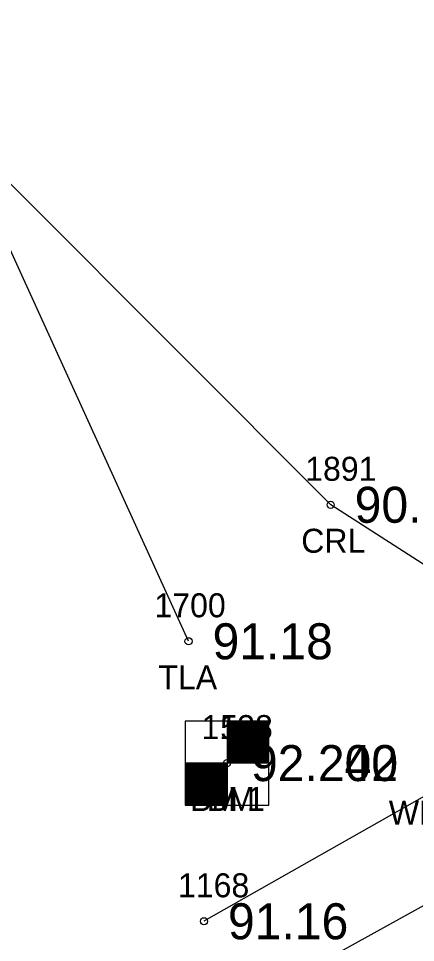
# Model space of a CAD drawing. Extents: x 2529517 to 2532038, y 935000 to 936944.
# Drawn here: x 2531058.87 to 2531075.43, y 935944.18 to 935982.7 of the extents above; entities that cross this region are included whole.
import ezdxf

# ---------------------------------------------------------------- set-up
doc = ezdxf.new("R2010")
doc.units = 0
for name, color, linetype in [('RD_EX_H2O', 7, 'Continuous'), ('RD_EX_H2O_txCode', 7, 'Continuous'), ('RD_EX_Road', 7, 'Continuous'), ('RD_EX_TX_H2O_ELEV', 7, 'Continuous'), ('RD_EX_TX_UT_ELEV', 7, 'Continuous'), ('RD_EX_TX_VEG_ELEV', 7, 'Continuous'), ('RD_EX_UT', 7, 'Continuous'), ('RD_EX_UT_txCode', 7, 'Continuous'), ('RD_EX_VEG', 7, 'Continuous'), ('RD_EX_VEG_txCode', 7, 'Continuous'), ('RD_HC_Survey', 7, 'Continuous'), ('RD_HC_Survey_ELEV', 7, 'Continuous'), ('RD_HC_Survey_txCode', 7, 'Continuous'), ('RD_SMD_Locator', 7, 'Continuous')]:
    doc.layers.add(name, color=color, linetype=linetype)

msp = doc.modelspace()

# ---------------------------------------------------------------- linework, layer by layer
at = {"layer": 'RD_EX_H2O'}
msp.add_lwpolyline([(2531078.875, 935952.281), (2531078.875, 935952.281), (2531082.899, 935955.367), (2531071.893, 935962.427), (2531052.521, 935981.817), (2531042.661, 936018.537), (2531050.401, 936038.586), (2531079.351, 936050.478), (2531076.459, 936052.289), (2531062.769, 936059.407), (2531060.273, 936060.115), (2531061.981, 936077.759), (2531053.988, 936081.477), (2531023.23, 936060.573), (2531009.04, 936063.638), (2530981.915, 936072.848), (2530952.276, 936069.689), (2530922.526, 936086.42), (2530896.36, 936118.007), (2530886.535, 936120.086), (2530870.436, 936126.503), (2530844.881, 936119.109), (2530827.398, 936131.929), (2530794.882, 936161.74)], dxfattribs=at)
at = {"layer": 'RD_EX_Road'}
msp.add_lwpolyline([(2530213.129, 935600.159), (2530313.796, 935600.808), (2530414.146, 935601.135), (2530426.724, 935601.431), (2530429.462, 935603.551), (2530467.667, 935608.622), (2530486.463, 935612.382), (2530518.022, 935622.553), (2530522.163, 935623.679), (2530567.909, 935646.012), (2530609.299, 935670.154), (2530695.461, 935720.024), (2530775.853, 935769.269), (2530868.285, 935824.026), (2530924.837, 935856.951), (2530956.207, 935875.821), (2531040.717, 935926.378), (2531079.452, 935947.762)], dxfattribs=at)
at = {"layer": 'RD_EX_UT'}
msp.add_line((2531077.223, 935951.092), (2531066.609, 935945.067), dxfattribs=at)
at = {"layer": 'RD_EX_VEG'}
msp.add_lwpolyline([(2531065.966, 935956.737), (2531029.723, 936036.27), (2530913.111, 935955.889), (2530857.851, 935929.004), (2530845.595, 935970.773)], dxfattribs=at)
at = {"layer": 'RD_HC_Survey'}
for p, q in [((2531067.569, 935953.41), (2531067.569, 935949.91)), ((2531067.569, 935953.41), (2531067.569, 935949.91)), ((2531067.586, 935953.41), (2531067.586, 935951.66)), ((2531067.586, 935953.41), (2531067.586, 935951.66)), ((2531067.611, 935953.41), (2531067.611, 935951.66)), ((2531067.611, 935953.41), (2531067.611, 935951.66)), ((2531067.636, 935953.41), (2531067.636, 935951.66)), ((2531067.636, 935953.41), (2531067.636, 935951.66)), ((2531067.661, 935953.41), (2531067.661, 935951.66)), ((2531067.661, 935953.41), (2531067.661, 935951.66)), ((2531067.685, 935953.41), (2531067.685, 935951.66)), ((2531067.685, 935953.41), (2531067.685, 935951.66)), ((2531067.71, 935953.41), (2531067.71, 935951.66)), ((2531067.71, 935953.41), (2531067.71, 935951.66)), ((2531067.735, 935953.41), (2531067.735, 935951.66)), ((2531067.735, 935953.41), (2531067.735, 935951.66)), ((2531067.76, 935953.41), (2531067.76, 935951.66)), ((2531067.76, 935953.41), (2531067.76, 935951.66)), ((2531067.784, 935953.41), (2531067.784, 935951.66)), ((2531067.784, 935953.41), (2531067.784, 935951.66)), ((2531067.809, 935953.41), (2531067.809, 935951.66)), ((2531067.809, 935953.41), (2531067.809, 935951.66)), ((2531067.834, 935953.41), (2531067.834, 935951.66)), ((2531067.834, 935953.41), (2531067.834, 935951.66)), ((2531067.859, 935953.41), (2531067.859, 935951.66)), ((2531067.859, 935953.41), (2531067.859, 935951.66)), ((2531067.883, 935953.41), (2531067.883, 935951.66)), ((2531067.883, 935953.41), (2531067.883, 935951.66)), ((2531067.908, 935953.41), (2531067.908, 935951.66)), ((2531067.908, 935953.41), (2531067.908, 935951.66)), ((2531067.933, 935953.41), (2531067.933, 935951.66)), ((2531067.933, 935953.41), (2531067.933, 935951.66)), ((2531067.958, 935953.41), (2531067.958, 935951.66)), ((2531067.958, 935953.41), (2531067.958, 935951.66)), ((2531067.982, 935953.41), (2531067.982, 935951.66)), ((2531067.982, 935953.41), (2531067.982, 935951.66)), ((2531068.007, 935953.41), (2531068.007, 935951.66)), ((2531068.007, 935953.41), (2531068.007, 935951.66)), ((2531068.032, 935953.41), (2531068.032, 935951.66)), ((2531068.032, 935953.41), (2531068.032, 935951.66)), ((2531068.057, 935953.41), (2531068.057, 935951.66)), ((2531068.057, 935953.41), (2531068.057, 935951.66)), ((2531068.081, 935953.41), (2531068.081, 935951.66)), ((2531068.081, 935953.41), (2531068.081, 935951.66)), ((2531068.106, 935953.41), (2531068.106, 935951.66)), ((2531068.106, 935953.41), (2531068.106, 935951.66)), ((2531068.131, 935953.41), (2531068.131, 935951.66)), ((2531068.131, 935953.41), (2531068.131, 935951.66)), ((2531068.156, 935953.41), (2531068.156, 935951.66)), ((2531068.156, 935953.41), (2531068.156, 935951.66)), ((2531068.18, 935953.41), (2531068.18, 935951.66)), ((2531068.18, 935953.41), (2531068.18, 935951.66)), ((2531068.205, 935953.41), (2531068.205, 935951.66)), ((2531068.205, 935953.41), (2531068.205, 935951.66)), ((2531068.23, 935953.41), (2531068.23, 935951.66)), ((2531068.23, 935953.41), (2531068.23, 935951.66)), ((2531068.255, 935953.41), (2531068.255, 935951.66)), ((2531068.255, 935953.41), (2531068.255, 935951.66)), ((2531068.279, 935953.41), (2531068.279, 935951.66)), ((2531068.279, 935953.41), (2531068.279, 935951.66)), ((2531068.304, 935953.41), (2531068.304, 935951.66)), ((2531068.304, 935953.41), (2531068.304, 935951.66)), ((2531068.329, 935953.41), (2531068.329, 935951.66)), ((2531068.329, 935953.41), (2531068.329, 935951.66)), ((2531068.354, 935953.41), (2531068.354, 935951.66)), ((2531068.354, 935953.41), (2531068.354, 935951.66)), ((2531068.378, 935953.41), (2531068.378, 935951.66)), ((2531068.378, 935953.41), (2531068.378, 935951.66)), ((2531068.403, 935953.41), (2531068.403, 935951.66)), ((2531068.403, 935953.41), (2531068.403, 935951.66)), ((2531068.428, 935953.41), (2531068.428, 935951.66)), ((2531068.428, 935953.41), (2531068.428, 935951.66)), ((2531068.453, 935953.41), (2531068.453, 935951.66)), ((2531068.453, 935953.41), (2531068.453, 935951.66)), ((2531068.477, 935953.41), (2531068.477, 935951.66)), ((2531068.477, 935953.41), (2531068.477, 935951.66)), ((2531068.502, 935953.41), (2531068.502, 935951.66)), ((2531068.502, 935953.41), (2531068.502, 935951.66)), ((2531068.527, 935953.41), (2531068.527, 935951.66)), ((2531068.527, 935953.41), (2531068.527, 935951.66)), ((2531068.552, 935953.41), (2531068.552, 935951.66)), ((2531068.552, 935953.41), (2531068.552, 935951.66)), ((2531068.576, 935953.41), (2531068.576, 935951.66)), ((2531068.576, 935953.41), (2531068.576, 935951.66)), ((2531068.601, 935953.41), (2531068.601, 935951.66)), ((2531068.601, 935953.41), (2531068.601, 935951.66)), ((2531068.626, 935953.41), (2531068.626, 935951.66)), ((2531068.626, 935953.41), (2531068.626, 935951.66)), ((2531068.651, 935953.41), (2531068.651, 935951.66)), ((2531068.651, 935953.41), (2531068.651, 935951.66)), ((2531068.675, 935953.41), (2531068.675, 935951.66)), ((2531068.675, 935953.41), (2531068.675, 935951.66)), ((2531068.7, 935953.41), (2531068.7, 935951.66)), ((2531068.7, 935953.41), (2531068.7, 935951.66)), ((2531068.725, 935953.41), (2531068.725, 935951.66)), ((2531068.725, 935953.41), (2531068.725, 935951.66)), ((2531068.75, 935953.41), (2531068.75, 935951.66)), ((2531068.75, 935953.41), (2531068.75, 935951.66)), ((2531068.774, 935953.41), (2531068.774, 935951.66)), ((2531068.774, 935953.41), (2531068.774, 935951.66)), ((2531068.799, 935953.41), (2531068.799, 935951.66)), ((2531068.799, 935953.41), (2531068.799, 935951.66)), ((2531068.824, 935953.41), (2531068.824, 935951.66)), ((2531068.824, 935953.41), (2531068.824, 935951.66)), ((2531068.849, 935953.41), (2531068.849, 935951.66)), ((2531068.849, 935953.41), (2531068.849, 935951.66)), ((2531068.873, 935953.41), (2531068.873, 935951.66)), ((2531068.873, 935953.41), (2531068.873, 935951.66)), ((2531068.898, 935953.41), (2531068.898, 935951.66)), ((2531068.898, 935953.41), (2531068.898, 935951.66)), ((2531068.923, 935953.41), (2531068.923, 935951.66)), ((2531068.923, 935953.41), (2531068.923, 935951.66)), ((2531068.948, 935953.41), (2531068.948, 935951.66)), ((2531068.948, 935953.41), (2531068.948, 935951.66)), ((2531068.972, 935953.41), (2531068.972, 935951.66)), ((2531068.972, 935953.41), (2531068.972, 935951.66)), ((2531068.997, 935953.41), (2531068.997, 935951.66)), ((2531068.997, 935953.41), (2531068.997, 935951.66)), ((2531069.022, 935953.41), (2531069.022, 935951.66)), ((2531069.022, 935953.41), (2531069.022, 935951.66)), ((2531069.047, 935953.41), (2531069.047, 935951.66)), ((2531069.047, 935953.41), (2531069.047, 935951.66)), ((2531069.071, 935953.41), (2531069.071, 935951.66)), ((2531069.071, 935953.41), (2531069.071, 935951.66)), ((2531069.096, 935953.41), (2531069.096, 935951.66)), ((2531069.096, 935953.41), (2531069.096, 935951.66)), ((2531069.121, 935953.41), (2531069.121, 935951.66)), ((2531069.121, 935953.41), (2531069.121, 935951.66)), ((2531069.146, 935953.41), (2531069.146, 935951.66)), ((2531069.146, 935953.41), (2531069.146, 935951.66)), ((2531069.17, 935953.41), (2531069.17, 935951.66)), ((2531069.17, 935953.41), (2531069.17, 935951.66)), ((2531069.195, 935953.41), (2531069.195, 935951.66)), ((2531069.195, 935953.41), (2531069.195, 935951.66)), ((2531069.22, 935953.41), (2531069.22, 935951.66)), ((2531069.22, 935953.41), (2531069.22, 935951.66)), ((2531069.245, 935953.41), (2531069.245, 935951.66)), ((2531069.245, 935953.41), (2531069.245, 935951.66)), ((2531069.269, 935953.41), (2531069.269, 935951.66)), ((2531069.269, 935953.41), (2531069.269, 935951.66)), ((2531069.294, 935953.41), (2531069.294, 935951.66)), ((2531069.294, 935953.41), (2531069.294, 935951.66)), ((2531069.319, 935951.66), (2531065.819, 935951.66)), ((2531065.819, 935951.66), (2531065.819, 935949.91)), ((2531069.319, 935951.66), (2531065.819, 935951.66)), ((2531065.819, 935951.66), (2531065.819, 935949.91)), ((2531065.844, 935951.66), (2531065.844, 935949.91)), ((2531065.844, 935951.66), (2531065.844, 935949.91)), ((2531065.868, 935951.66), (2531065.868, 935949.91)), ((2531065.868, 935951.66), (2531065.868, 935949.91)), ((2531065.893, 935951.66), (2531065.893, 935949.91)), ((2531065.893, 935951.66), (2531065.893, 935949.91)), ((2531065.918, 935951.66), (2531065.918, 935949.91)), ((2531065.918, 935951.66), (2531065.918, 935949.91)), ((2531065.943, 935951.66), (2531065.943, 935949.91)), ((2531065.943, 935951.66), (2531065.943, 935949.91)), ((2531065.967, 935951.66), (2531065.967, 935949.91)), ((2531065.967, 935951.66), (2531065.967, 935949.91)), ((2531065.992, 935951.66), (2531065.992, 935949.91)), ((2531065.992, 935951.66), (2531065.992, 935949.91)), ((2531066.017, 935951.66), (2531066.017, 935949.91)), ((2531066.017, 935951.66), (2531066.017, 935949.91)), ((2531066.042, 935951.66), (2531066.042, 935949.91)), ((2531066.042, 935951.66), (2531066.042, 935949.91)), ((2531066.066, 935951.66), (2531066.066, 935949.91)), ((2531066.066, 935951.66), (2531066.066, 935949.91)), ((2531066.091, 935951.66), (2531066.091, 935949.91)), ((2531066.091, 935951.66), (2531066.091, 935949.91)), ((2531066.116, 935951.66), (2531066.116, 935949.91)), ((2531066.116, 935951.66), (2531066.116, 935949.91)), ((2531066.141, 935951.66), (2531066.141, 935949.91)), ((2531066.141, 935951.66), (2531066.141, 935949.91)), ((2531066.165, 935951.66), (2531066.165, 935949.91)), ((2531066.165, 935951.66), (2531066.165, 935949.91)), ((2531066.19, 935951.66), (2531066.19, 935949.91)), ((2531066.19, 935951.66), (2531066.19, 935949.91)), ((2531066.215, 935951.66), (2531066.215, 935949.91)), ((2531066.215, 935951.66), (2531066.215, 935949.91)), ((2531066.24, 935951.66), (2531066.24, 935949.91)), ((2531066.24, 935951.66), (2531066.24, 935949.91)), ((2531066.264, 935951.66), (2531066.264, 935949.91)), ((2531066.264, 935951.66), (2531066.264, 935949.91)), ((2531066.289, 935951.66), (2531066.289, 935949.91)), ((2531066.289, 935951.66), (2531066.289, 935949.91)), ((2531066.314, 935951.66), (2531066.314, 935949.91)), ((2531066.314, 935951.66), (2531066.314, 935949.91)), ((2531066.339, 935951.66), (2531066.339, 935949.91)), ((2531066.339, 935951.66), (2531066.339, 935949.91)), ((2531066.363, 935951.66), (2531066.363, 935949.91)), ((2531066.363, 935951.66), (2531066.363, 935949.91)), ((2531066.388, 935951.66), (2531066.388, 935949.91)), ((2531066.388, 935951.66), (2531066.388, 935949.91)), ((2531066.413, 935951.66), (2531066.413, 935949.91)), ((2531066.413, 935951.66), (2531066.413, 935949.91)), ((2531066.438, 935951.66), (2531066.438, 935949.91)), ((2531066.438, 935951.66), (2531066.438, 935949.91)), ((2531066.462, 935951.66), (2531066.462, 935949.91)), ((2531066.462, 935951.66), (2531066.462, 935949.91)), ((2531066.487, 935951.66), (2531066.487, 935949.91)), ((2531066.487, 935951.66), (2531066.487, 935949.91)), ((2531066.512, 935951.66), (2531066.512, 935949.91)), ((2531066.512, 935951.66), (2531066.512, 935949.91)), ((2531066.537, 935951.66), (2531066.537, 935949.91)), ((2531066.537, 935951.66), (2531066.537, 935949.91)), ((2531066.561, 935951.66), (2531066.561, 935949.91)), ((2531066.561, 935951.66), (2531066.561, 935949.91)), ((2531066.586, 935951.66), (2531066.586, 935949.91)), ((2531066.586, 935951.66), (2531066.586, 935949.91)), ((2531066.611, 935951.66), (2531066.611, 935949.91)), ((2531066.611, 935951.66), (2531066.611, 935949.91)), ((2531066.636, 935951.66), (2531066.636, 935949.91)), ((2531066.636, 935951.66), (2531066.636, 935949.91)), ((2531066.66, 935951.66), (2531066.66, 935949.91)), ((2531066.66, 935951.66), (2531066.66, 935949.91)), ((2531066.685, 935951.66), (2531066.685, 935949.91)), ((2531066.685, 935951.66), (2531066.685, 935949.91)), ((2531066.71, 935951.66), (2531066.71, 935949.91)), ((2531066.71, 935951.66), (2531066.71, 935949.91)), ((2531066.735, 935951.66), (2531066.735, 935949.91)), ((2531066.735, 935951.66), (2531066.735, 935949.91)), ((2531066.759, 935951.66), (2531066.759, 935949.91)), ((2531066.759, 935951.66), (2531066.759, 935949.91)), ((2531066.784, 935951.66), (2531066.784, 935949.91)), ((2531066.784, 935951.66), (2531066.784, 935949.91)), ((2531066.809, 935951.66), (2531066.809, 935949.91)), ((2531066.809, 935951.66), (2531066.809, 935949.91)), ((2531066.834, 935951.66), (2531066.834, 935949.91)), ((2531066.834, 935951.66), (2531066.834, 935949.91)), ((2531066.858, 935951.66), (2531066.858, 935949.91)), ((2531066.858, 935951.66), (2531066.858, 935949.91)), ((2531066.883, 935951.66), (2531066.883, 935949.91)), ((2531066.883, 935951.66), (2531066.883, 935949.91)), ((2531066.908, 935951.66), (2531066.908, 935949.91)), ((2531066.908, 935951.66), (2531066.908, 935949.91)), ((2531066.932, 935951.66), (2531066.932, 935949.91)), ((2531066.932, 935951.66), (2531066.932, 935949.91)), ((2531066.957, 935951.66), (2531066.957, 935949.91)), ((2531066.957, 935951.66), (2531066.957, 935949.91)), ((2531066.982, 935951.66), (2531066.982, 935949.91)), ((2531066.982, 935951.66), (2531066.982, 935949.91)), ((2531067.007, 935951.66), (2531067.007, 935949.91)), ((2531067.007, 935951.66), (2531067.007, 935949.91)), ((2531067.031, 935951.66), (2531067.031, 935949.91)), ((2531067.031, 935951.66), (2531067.031, 935949.91)), ((2531067.056, 935951.66), (2531067.056, 935949.91)), ((2531067.056, 935951.66), (2531067.056, 935949.91)), ((2531067.081, 935951.66), (2531067.081, 935949.91)), ((2531067.081, 935951.66), (2531067.081, 935949.91)), ((2531067.106, 935951.66), (2531067.106, 935949.91)), ((2531067.106, 935951.66), (2531067.106, 935949.91)), ((2531067.13, 935951.66), (2531067.13, 935949.91)), ((2531067.13, 935951.66), (2531067.13, 935949.91)), ((2531067.155, 935951.66), (2531067.155, 935949.91)), ((2531067.155, 935951.66), (2531067.155, 935949.91)), ((2531067.18, 935951.66), (2531067.18, 935949.91)), ((2531067.18, 935951.66), (2531067.18, 935949.91)), ((2531067.205, 935951.66), (2531067.205, 935949.91)), ((2531067.205, 935951.66), (2531067.205, 935949.91)), ((2531067.229, 935951.66), (2531067.229, 935949.91)), ((2531067.229, 935951.66), (2531067.229, 935949.91)), ((2531067.254, 935951.66), (2531067.254, 935949.91)), ((2531067.254, 935951.66), (2531067.254, 935949.91)), ((2531067.279, 935951.66), (2531067.279, 935949.91)), ((2531067.279, 935951.66), (2531067.279, 935949.91)), ((2531067.304, 935951.66), (2531067.304, 935949.91)), ((2531067.304, 935951.66), (2531067.304, 935949.91)), ((2531067.328, 935951.66), (2531067.328, 935949.91)), ((2531067.328, 935951.66), (2531067.328, 935949.91)), ((2531067.353, 935951.66), (2531067.353, 935949.91)), ((2531067.353, 935951.66), (2531067.353, 935949.91)), ((2531067.378, 935951.66), (2531067.378, 935949.91)), ((2531067.378, 935951.66), (2531067.378, 935949.91)), ((2531067.403, 935951.66), (2531067.403, 935949.91)), ((2531067.403, 935951.66), (2531067.403, 935949.91)), ((2531067.427, 935951.66), (2531067.427, 935949.91)), ((2531067.427, 935951.66), (2531067.427, 935949.91)), ((2531067.452, 935951.66), (2531067.452, 935949.91)), ((2531067.452, 935951.66), (2531067.452, 935949.91)), ((2531067.477, 935951.66), (2531067.477, 935949.91)), ((2531067.477, 935951.66), (2531067.477, 935949.91)), ((2531067.502, 935951.66), (2531067.502, 935949.91)), ((2531067.502, 935951.66), (2531067.502, 935949.91)), ((2531067.526, 935951.66), (2531067.526, 935949.91)), ((2531067.526, 935951.66), (2531067.526, 935949.91)), ((2531067.551, 935951.66), (2531067.551, 935949.91)), ((2531067.551, 935951.66), (2531067.551, 935949.91))]:
    msp.add_line(p, q, dxfattribs=at)
msp.add_lwpolyline([(2531069.319, 935953.41), (2531065.819, 935953.41), (2531065.819, 935949.91), (2531069.319, 935949.91)], close=True, dxfattribs=at)
msp.add_lwpolyline([(2531069.319, 935953.41), (2531065.819, 935953.41), (2531065.819, 935949.91), (2531069.319, 935949.91)], close=True, dxfattribs=at)
at = {"layer": 'RD_SMD_Locator'}
for centre in [(2531071.893, 935962.427), (2531065.966, 935956.737), (2531067.569, 935951.66), (2531067.569, 935951.66), (2531066.609, 935945.067)]:
    msp.add_circle(centre, 0.15, dxfattribs=at)

# ---------------------------------------------------------------- texts
at = {"layer": 'RD_EX_H2O_txCode'}
for s, p in [('1891', (2531070.83, 935963.427)), ('CRL', (2531070.665, 935960.427))]:
    msp.add_text(s, height=1, dxfattribs=at).set_placement(p)
at = {"layer": 'RD_EX_TX_H2O_ELEV'}
msp.add_text('90.86', height=1.5, dxfattribs=at).set_placement((2531072.893, 935961.677))
at = {"layer": 'RD_EX_TX_UT_ELEV'}
msp.add_text('91.16', height=1.5, dxfattribs=at).set_placement((2531067.609, 935944.317))
at = {"layer": 'RD_EX_TX_VEG_ELEV'}
msp.add_text('91.18', height=1.5, dxfattribs=at).set_placement((2531066.966, 935955.987))
at = {"layer": 'RD_EX_UT_txCode'}
for s, p in [('WLA 6CI', (2531074.317, 935949.092)), ('1168', (2531065.523, 935946.067))]:
    msp.add_text(s, height=1, dxfattribs=at).set_placement(p)
at = {"layer": 'RD_EX_VEG_txCode'}
for s, p in [('1700', (2531064.541, 935957.737)), ('TLA', (2531064.706, 935954.737))]:
    msp.add_text(s, height=1, dxfattribs=at).set_placement(p)
at = {"layer": 'RD_HC_Survey_ELEV'}
for s in ['92.200', '92.242']:
    msp.add_text(s, height=1.5, dxfattribs=at).set_placement((2531068.569, 935950.91))
at = {"layer": 'RD_HC_Survey_txCode'}
for s, p in [('1138', (2531066.506, 935952.66)), ('5', (2531067.285, 935952.66)), ('BM 1', (2531066.025, 935949.66)), ('BM', (2531066.726, 935949.66))]:
    msp.add_text(s, height=1, dxfattribs=at).set_placement(p)

doc.saveas('drawing.dxf')
